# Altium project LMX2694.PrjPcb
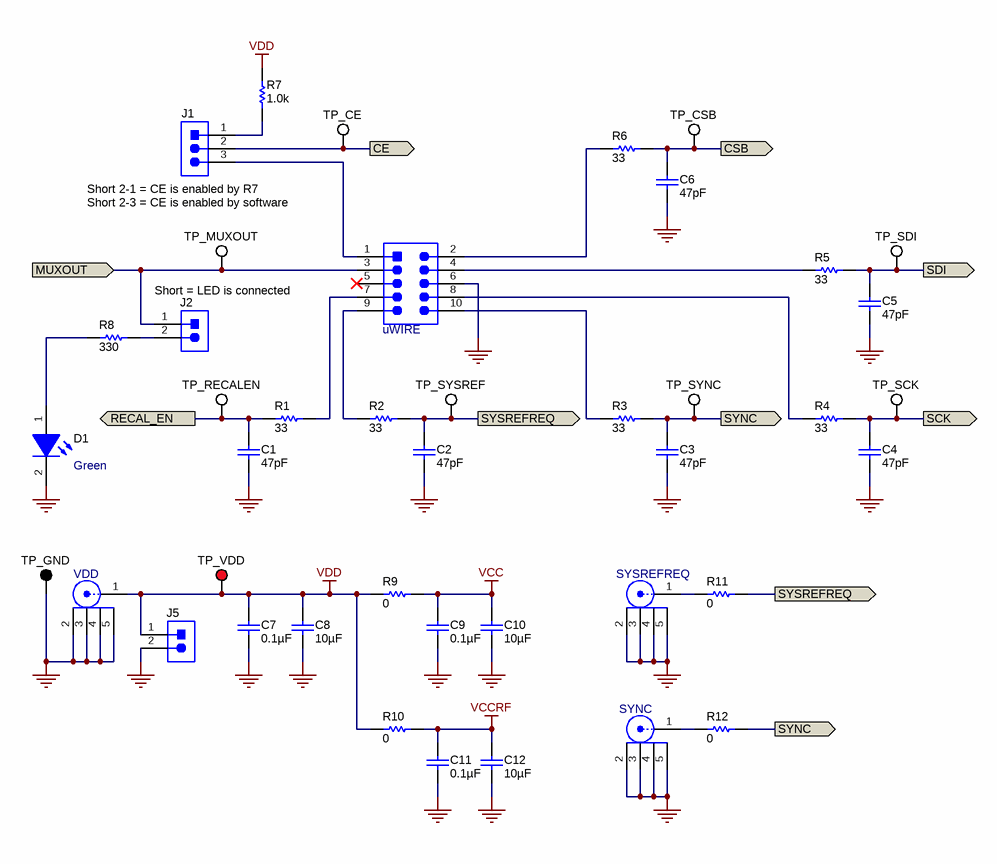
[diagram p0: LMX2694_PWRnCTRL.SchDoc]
CopyrightYear: 2019; PCB_Rev: A; PRJ_Customer: Public Release; PRJ_Title: LMX2694 EVM; SCH_Rev: A; TechSupport: http://www.ti.com/support; TID: N/A
3 sheets, 109 parts. Net scope: flat (ports and power ports of the same name join across sheets).
Board file: LMX2694.PcbDoc
Sheets:
  LMX2694_PWRnCTRL.SchDoc
  LMX2694_SYNTH.SchDoc
  LMX2694_HW.SchDoc

## Sheet LMX2694_PWRnCTRL.SchDoc: Power supply and control interface
size Letter; Date: Not shown in title block; ApprovedBy: Not shown in title block; CheckedBy: Not shown in title block; Author: Not shown in title block; CompanyName: Not shown in title block; Engineer: Not shown in title block; Organization: Not shown in title block; Address1: Not shown in title block; Address2: Not shown in title block; Address3: Not shown in title block; Address4: Not shown in title block; DocumentNumber: 1; Revision: Use project parameter SCH_Rev; SheetNumber: 1; SheetTotal: 3; PageSetup: Record=PageOptions¦CenterHorizontal=True¦CenterVertical=True¦PrintScale=1.00¦XCorrection=1.00¦YCorrection=1.00¦PrintKind=0¦BorderSize=5000000¦LeftOffset=0¦BottomOffset=0¦Orientation=2¦PaperLength=1000¦PaperWidth=1000¦Scale=100¦PaperSource=15¦PrintQuality=600¦MediaType=1¦DitherType=10¦PaperKind=Letter¦PrintScaleMode=1

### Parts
C1  ValueDisplayed: 47pF  [0402]  (hidden comment: 885012005044)
C2  ValueDisplayed: 47pF  [0402]  (hidden comment: 885012005044)
C3  ValueDisplayed: 47pF  [0402]  (hidden comment: 885012005044)
C4  ValueDisplayed: 47pF  [0402]  (hidden comment: 885012005044)
C5  ValueDisplayed: 47pF  [0402]  (hidden comment: 885012005044)
C6  ValueDisplayed: 47pF  [0402]  (hidden comment: 885012005044)
C7  ValueDisplayed: 0.1µF  [0603]  (hidden comment: 885012206046)
C8  ValueDisplayed: 10µF  [0603]  (hidden comment: GRM188R61A106KAALD)
C9  ValueDisplayed: 0.1µF  [0603]  (hidden comment: 885012206046)
C10  ValueDisplayed: 10µF  [0603]  (hidden comment: GRM188R61A106KAALD)
C11  ValueDisplayed: 0.1µF  [0603]  (hidden comment: 885012206046)
C12  ValueDisplayed: 10µF  [0603]  (hidden comment: GRM188R61A106KAALD)
D1  value Green  [LED_LTST-C190]  (hidden comment: LTST-C190GKT)
J1  TSW-103-07-G-S  [TSW-103-07-G-S]  (value not drawn)
J2  TSW-102-07-G-S  [TSW-102-07-G-S]  (value not drawn)
J3  uWIRE  [FCI_52601-S10-8LF]
J4  VDD  [FP-CON-SMA-EDGE-S_CONN_JACK-MFG]
J5  TSW-102-07-G-S  [TSW-102-07-G-S]  (value not drawn)
J6  SYSREFREQ  [FP-CON-SMA-EDGE-S_CONN_JACK-MFG]
J7  SYNC  [FP-CON-SMA-EDGE-S_CONN_JACK-MFG]
R1  ValueDisplayed: 33  [0603]  (hidden comment: CRCW060333R0JNEA)
R2  ValueDisplayed: 33  [0603]  (hidden comment: CRCW060333R0JNEA)
R3  ValueDisplayed: 33  [0603]  (hidden comment: CRCW060333R0JNEA)
R4  ValueDisplayed: 33  [0603]  (hidden comment: CRCW060333R0JNEA)
R5  ValueDisplayed: 33  [0603]  (hidden comment: CRCW060333R0JNEA)
R6  ValueDisplayed: 33  [0603]  (hidden comment: CRCW060333R0JNEA)
R7  ValueDisplayed: 1.0k  [0603]  (hidden comment: CRCW06031K00JNEA)
R8  ValueDisplayed: 330  [0603]  (hidden comment: CRCW0603330RJNEA)
R9  ValueDisplayed: 0  [0603]  (hidden comment: CRCW06030000Z0EA)
R10  ValueDisplayed: 0  [0603]  (hidden comment: CRCW06030000Z0EA)
R11  ValueDisplayed: 0  [0603]  (hidden comment: CRCW06030000Z0EA)
R12  ValueDisplayed: 0  [0603]  (hidden comment: CRCW06030000Z0EA)
TP1  TP_CE  [Keystone5002]
TP2  TP_CSB  [Keystone5002]
TP3  TP_MUXOUT  [Keystone5002]
TP4  TP_SDI  [Keystone5002]
TP5  TP_RECALEN  [Keystone5002]
TP6  TP_SYSREF  [Keystone5002]
TP7  TP_SYNC  [Keystone5002]
TP8  TP_SCK  [Keystone5002]
TP9  TP_GND  [Keystone5001]
TP10  TP_VDD  [Keystone5000]

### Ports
CE (out), CSB (out), MUXOUT (in), RECAL_EN (out), SCK (out), SDI (out), SYNC (out), SYSREFREQ (out)

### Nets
GND: C1.2 C2.2 C3.2 C4.2 C5.2 C6.2 C7.2 C8.2 C9.2 C10.2 C11.2 C12.2 D1.2(K) J3.6 J4.2 J4.3 J4.4 J4.5 J5.2 J6.2 J6.3 J6.4 J6.5 J7.2 J7.3 J7.4 J7.5 TP9.1
VCC: C9.1 C10.1 R9.2
VCCRF: C11.1 C12.1 R10.2
VDD: C7.1 C8.1 J4.1 J5.1 R7.2 R9.1 R10.1 TP10.1
CE: J1.2 TP1.1 ; port CE
CSB: C6.1 R6.2 TP2.1 ; port CSB
MUXOUT: J2.1 J3.3 TP3.1 ; port MUXOUT
RECAL_EN: C1.1 R1.1 TP5.1 ; port RECAL_EN
SCK: C4.1 R4.2 TP8.1 ; port SCK
SDI: C5.1 R5.2 TP4.1 ; port SDI
SYNC: C3.1 R3.2 R12.2 TP7.1 ; port SYNC
SYSREFREQ: C2.1 R2.2 R11.2 TP6.1 ; port SYSREFREQ
NetD1_1: D1.1(A) R8.2
NetJ1_1: J1.1 R7.1
NetJ1_3: J1.3 J3.1
NetJ2_2: J2.2 R8.1
NetJ3_2: J3.2 R6.1
NetJ3_4: J3.4 R5.1
NetJ3_7: J3.7 R1.2
NetJ3_8: J3.8 R4.1
NetJ3_9: J3.9 R2.1
NetJ3_10: J3.10 R3.1
NetJ6_1: J6.1 R11.1
NetJ7_1: J7.1 R12.1

Not connected (* = marked no-connect by the designer): J3 5*

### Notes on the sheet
- (near J1) Short 2-1 = CE is enabled by R7
- Short 2-3 = CE is enabled by software
- Short = LED is connected

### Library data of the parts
C1-C6 = CMP-0006214-2: CAP, CERM, 47 pF, 50 V, +/- 5%, C0G/NP0, 0402; Manufacturer: Wurth Elektronik; TaMin_C: -55°C; Polarized: N; SizeAreaWB_mm2: 3; Value1: Unknown; U/M: EA; Value: 47pF; TaMax_C: 125°C; SizeZ_mm: 0.6; SizeX_mm: 1; SizeY_mm: 0.5; Value2: 50V; AEC Category: Q200
C7 C9 C11 = CMP-0006829-4: CAP, CERM, 0.1 uF, 16 V, +/- 10%, X7R, 0603; Manufacturer: Wurth Elektronik; TaMin_C: -55°C; Polarized: N; SizeAreaWB_mm2: 4.68; Value1: Unknown; U/M: EA; Value: 0.1uF; TaMax_C: 125°C; SizeZ_mm: 1; SizeX_mm: 1.6; SizeY_mm: 0.8; Value2: 16V; SizeArea_mm2: 1.28; Cap_F: 100nF; AEC Category: Q200
C8 C10 C12 = CMP-0086193-1: CAP, CERM, 10 µF, 10 V,+/- 10%, X5R, 0603; Manufacturer: MuRata; SizeArea_mm2: 1.28; SizeY_mm: 0.8; TaMax_C: 85°C; TaMin_C: -55°C; VDC_V: 10V; Polarized: N; SizeAreaWB_mm2: 4.68; SizeZ_mm: 1; SizeX_mm: 1.6; AEC Category: Q200; U/M: EA; Value: 10uF
D1 = CMP-0002827-3: LED, Green, SMD; Manufacturer: Lite-On; Power_TotalModule: 100mW; Value2: 2.1V; Io_A: 20mA; Value1: 0.1W
J1 = CMP-0075407-2: Header, 100mil, 3x1, Gold, TH; Manufacturer: Samtec; Pitch_mm: 2.54; Cert_VDE: N; Gender: Male; Cert_CSA: Y; Voltage_V: 550V; Green_REACh: Passed; Current_A: 6.3A; Green_Lifecycle: Active; Row_Count: 1
J2 J5 = CMP-0075405-2: Header, 100mil, 2x1, Gold, TH; Manufacturer: Samtec; Pitch_mm: 2.54; Cert_VDE: N; Gender: Male; Cert_CSA: Y; Voltage_V: 550V; Green_REACh: Passed; Current_A: 6.3A; Green_Lifecycle: Active; Row_Count: 1
J3 = CMP-0055434-2: Header (shrouded), 100mil, 5x2, Gold, SMT; Manufacturer: FCI; PartNumber: 52601-S10-8LF; Green_Lifecycle: Active; Green_REACh: Passed
J4 J6 J7 = CMP-0088000-3: CONN SMA JACK STR EDGE MNT; Manufacturer: RF Solutions Ltd.; PartNumber: CON-SMA-EDGE-S; ContactFinish: Gold; Shrouded: true
R1-R6 = CMP-0025787-4: RES, 33, 5%, 0.1 W, AEC-Q200 Grade 0, 0603; Manufacturer: Vishay-Dale; Power_W: 100mW; TempCo: 200 ppm/C; Value_Code: 33R0; Value: 33; EIA_Code: E24; SizeX_mm: 1.6; SizeY_mm: 0.8; SizeZ_mm: 1; Value2: 0.1W; SizeArea_mm2: 1.28; AEC Qualified: Y; VDC_V: 75V; AEC Category: Q200; AEC Grade: 0
R7 = CMP-0025729-4: RES, 1.0 k, 5%, 0.1 W, AEC-Q200 Grade 0, 0603; Manufacturer: Vishay-Dale; Power_W: 100mW; TempCo: 200 ppm/C; Value_Code: 1k00; Value: 1.0k; EIA_Code: E24; Res_ohm: 1k; SizeX_mm: 1.6; SizeY_mm: 0.8; SizeZ_mm: 1; Value2: 0.1W; SizeArea_mm2: 1.28; AEC Qualified: Y; VDC_V: 75V; AEC Category: Q200; AEC Grade: 0
R8 = CMP-0025785-4: RES, 330, 5%, 0.1 W, AEC-Q200 Grade 0, 0603; Manufacturer: Vishay-Dale; Power_W: 100mW; TempCo: 200 ppm/C; Value_Code: 330R; Value: 330; EIA_Code: E24; SizeX_mm: 1.6; SizeY_mm: 0.8; SizeZ_mm: 1; Value2: 0.1W; SizeArea_mm2: 1.28; AEC Qualified: Y; VDC_V: 75V; AEC Category: Q200; AEC Grade: 0
R9-R12 = CMP-0025697-4: RES, 0, 5%, 0.1 W, AEC-Q200 Grade 0, 0603; Manufacturer: Vishay-Dale; Power_W: 100mW; TempCo: 200 ppm/C; Value_Code: 0000; Value: 0; EIA_Code: E24; SizeX_mm: 1.6; SizeY_mm: 0.8; SizeZ_mm: 1; Value2: 0.1W; SizeArea_mm2: 1.28; AEC Qualified: Y; VDC_V: 75V; AEC Category: Q200
TP1-TP8 = CMP-0055139-1: Test Point, Miniature, White, TH; Manufacturer: Keystone; CNHeader: FALSE; Green_Lifecycle: Active; Green_REACh: Passed; ContactFinish: Silver; CT: TRUE
TP9 = CMP-0055138-1: Test Point, Miniature, Black, TH; Manufacturer: Keystone; CNHeader: FALSE; Green_Lifecycle: Active; Green_REACh: Passed; ContactFinish: Silver; CT: TRUE
TP10 = CMP-0055137-1: Test Point, Miniature, Red, TH; Manufacturer: Keystone; CNHeader: FALSE; Green_Lifecycle: Active; Green_REACh: Passed; ContactFinish: Silver; CT: TRUE

## Sheet LMX2694_SYNTH.SchDoc: Synthesizer
size Letter; Date: Not shown in title block; ApprovedBy: Not shown in title block; CheckedBy: Not shown in title block; Author: Not shown in title block; CompanyName: Not shown in title block; Engineer: Not shown in title block; Organization: Not shown in title block; Address1: Not shown in title block; Address2: Not shown in title block; Address3: Not shown in title block; Address4: Not shown in title block; DocumentNumber: 2; Revision: Use project parameter SCH_Rev; SheetNumber: 2; SheetTotal: 3; PageSetup: Record=PageOptions¦CenterHorizontal=True¦CenterVertical=True¦PrintScale=1.00¦XCorrection=1.00¦YCorrection=1.00¦PrintKind=0¦BorderSize=5000000¦LeftOffset=0¦BottomOffset=0¦Orientation=2¦PaperLength=1000¦PaperWidth=1000¦Scale=100¦PaperSource=15¦PrintQuality=600¦MediaType=1¦DitherType=10¦PaperKind=Letter¦PrintScaleMode=1
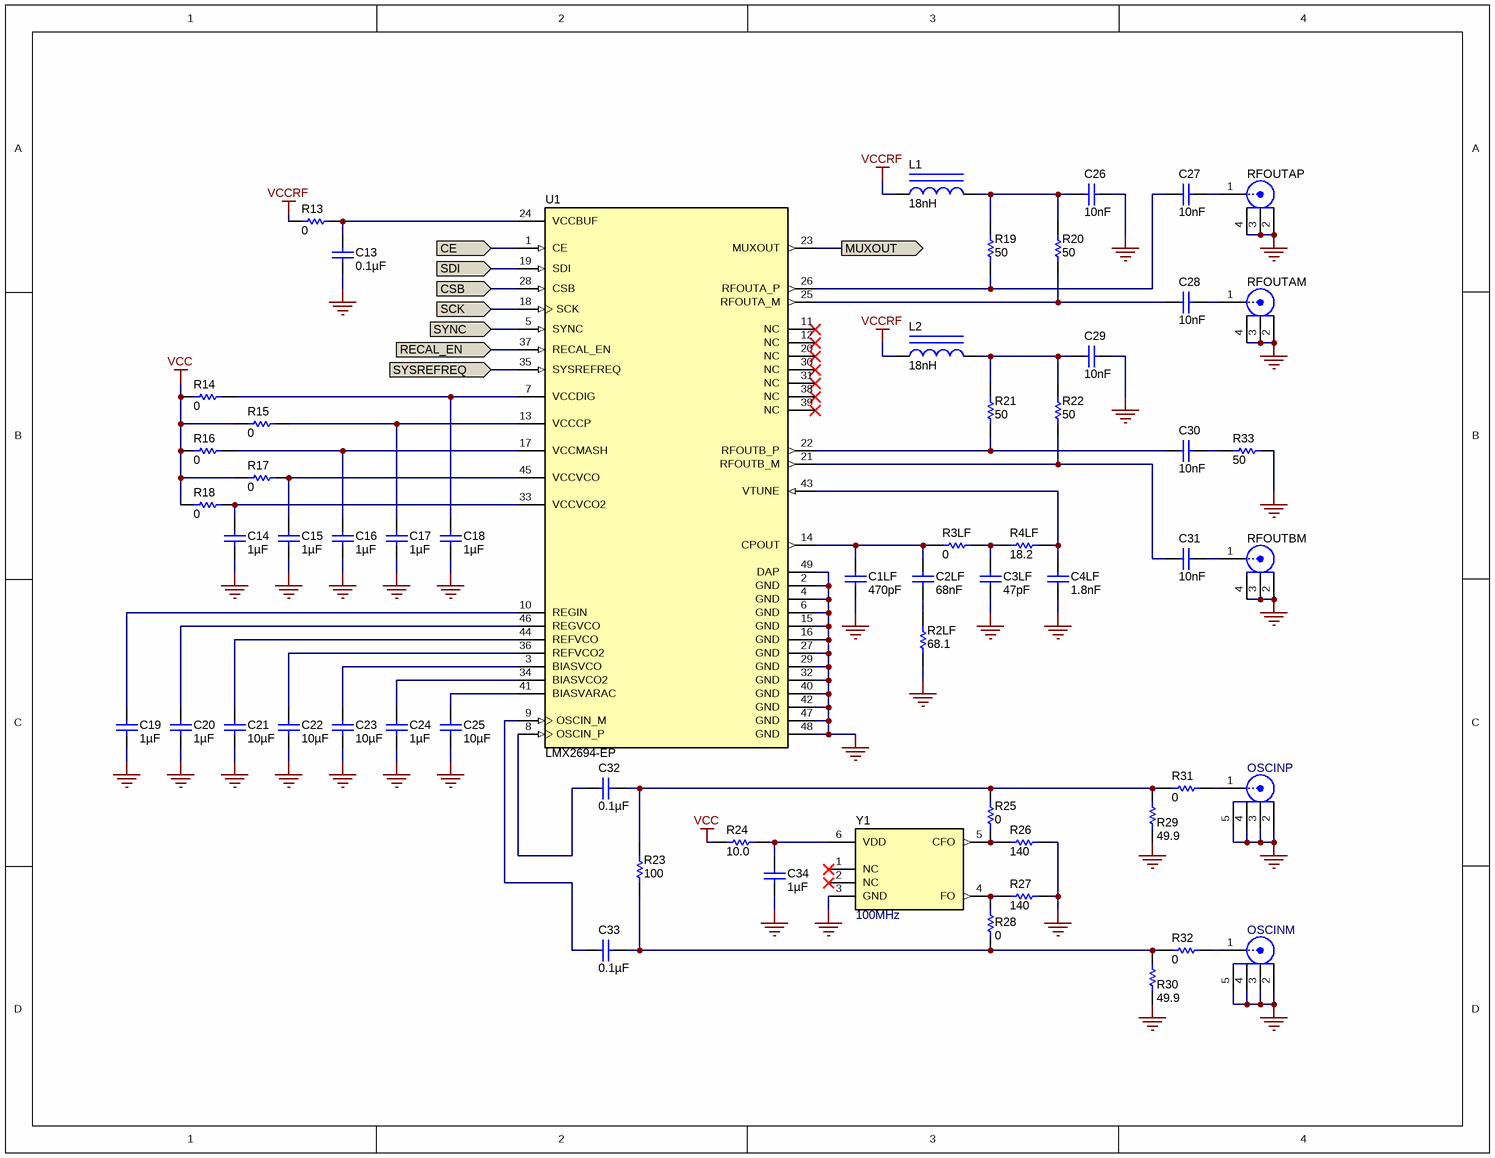
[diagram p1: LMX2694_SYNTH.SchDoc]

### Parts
C1LF  ValueDisplayed: 470pF  [0402]  (hidden comment: C0402C471K5GAC7867)
C2LF  ValueDisplayed: 68nF  [0402]  (hidden comment: CGA2B3X7R1H683K050BB)
C3LF  ValueDisplayed: 47pF  [0402]  (hidden comment: 885012005044)
C4LF  ValueDisplayed: 1.8nF  [0402]  (hidden comment: C0402C182J5RACTU)
C13  ValueDisplayed: 0.1µF  [0402]  (hidden comment: 885012205037)
C14  ValueDisplayed: 1µF  [0402]  (hidden comment: GRM155R61E105KA12D)
C15  ValueDisplayed: 1µF  [0402]  (hidden comment: GRM155R61E105KA12D)
C16  ValueDisplayed: 1µF  [0402]  (hidden comment: GRM155R61E105KA12D)
C17  ValueDisplayed: 1µF  [0402]  (hidden comment: GRM155R61E105KA12D)
C18  ValueDisplayed: 1µF  [0402]  (hidden comment: GRM155R61E105KA12D)
C19  ValueDisplayed: 1µF  [0402]  (hidden comment: GRM155R61E105KA12D)
C20  ValueDisplayed: 1µF  [0402]  (hidden comment: GRM155R61E105KA12D)
C21  ValueDisplayed: 10µF  [0603]  (hidden comment: GRM188R61A106KAALD)
C22  ValueDisplayed: 10µF  [0603]  (hidden comment: GRM188R61A106KAALD)
C23  ValueDisplayed: 10µF  [0603]  (hidden comment: GRM188R61A106KAALD)
C24  ValueDisplayed: 1µF  [0402]  (hidden comment: GRM155R61E105KA12D)
C25  ValueDisplayed: 10µF  [0603]  (hidden comment: GRM188R61A106KAALD)
C26  ValueDisplayed: 10nF  [0402_065]  (hidden comment: 520L103KT16T)
C27  ValueDisplayed: 10nF  [0402_065]  (hidden comment: 520L103KT16T)
C28  ValueDisplayed: 10nF  [0402_065]  (hidden comment: 520L103KT16T)
C29  ValueDisplayed: 10nF  [0402_065]  (hidden comment: 520L103KT16T)
C30  ValueDisplayed: 10nF  [0402_065]  (hidden comment: 520L103KT16T)
C31  ValueDisplayed: 10nF  [0402_065]  (hidden comment: 520L103KT16T)
C32  ValueDisplayed: 0.1µF  [0402]  (hidden comment: 885012205037)
C33  ValueDisplayed: 0.1µF  [0402]  (hidden comment: 885012205037)
C34  ValueDisplayed: 1µF  [0402]  (hidden comment: GRM155R61E105KA12D)
J8  RFOUTAP  [Johnson_142-0771-831]
J9  RFOUTAM  [Johnson_142-0771-831]
J10  RFOUTBM  [Johnson_142-0771-831]
J12  OSCINP  [FP-CON-SMA-EDGE-S_CONN_JACK-MFG]
J13  OSCINM  [FP-CON-SMA-EDGE-S_CONN_JACK-MFG]
L1  ValueDisplayed: 18nH  [IND_LQG15H]  (hidden comment: LQG15HS18NJ02D)
L2  ValueDisplayed: 18nH  [IND_LQG15H]  (hidden comment: LQG15HS18NJ02D)
R2LF  ValueDisplayed: 68.1  [0402]  (hidden comment: CRCW040268R1FKED)
R3LF  ValueDisplayed: 0  [0402]  (hidden comment: CRCW04020000Z0ED)
R4LF  ValueDisplayed: 18.2  [0402]  (hidden comment: CRCW040218R2FKED)
R13  ValueDisplayed: 0  [0402]  (hidden comment: CRCW04020000Z0ED)
R14  ValueDisplayed: 0  [0402]  (hidden comment: CRCW04020000Z0ED)
R15  ValueDisplayed: 0  [0402]  (hidden comment: CRCW04020000Z0ED)
R16  ValueDisplayed: 0  [0402]  (hidden comment: CRCW04020000Z0ED)
R17  ValueDisplayed: 0  [0402]  (hidden comment: CRCW04020000Z0ED)
R18  ValueDisplayed: 0  [0402]  (hidden comment: CRCW04020000Z0ED)
R19  ValueDisplayed: 50  [0402]  (hidden comment: FC0402E50R0BST1)
R20  ValueDisplayed: 50  [0402]  (hidden comment: FC0402E50R0BST1)
R21  ValueDisplayed: 50  [0402]  (hidden comment: FC0402E50R0BST1)
R22  ValueDisplayed: 50  [0402]  (hidden comment: FC0402E50R0BST1)
R23  ValueDisplayed: 100  [0402]  (hidden comment: CRCW0402100RFKED)
R24  ValueDisplayed: 10.0  [0402]  (hidden comment: CRCW040210R0FKED)
R25  ValueDisplayed: 0  [0402]  (hidden comment: CRCW04020000Z0ED)
R26  ValueDisplayed: 140  [0402]  (hidden comment: CRCW0402140RFKED)
R27  ValueDisplayed: 140  [0402]  (hidden comment: CRCW0402140RFKED)
R28  ValueDisplayed: 0  [0402]  (hidden comment: CRCW04020000Z0ED)
R29  ValueDisplayed: 49.9  [0402]  (hidden comment: CRCW040249R9FKED)
R30  ValueDisplayed: 49.9  [0402]  (hidden comment: CRCW040249R9FKED)
R31  ValueDisplayed: 0  [0402]  (hidden comment: CRCW04020000Z0ED)
R32  ValueDisplayed: 0  [0402]  (hidden comment: CRCW04020000Z0ED)
R33  ValueDisplayed: 50  [0402]  (hidden comment: FC0402E50R0BST1)
U1  LMX2694-EP  [RTC0048A]
Y1  100MHz  [Vectron_VC-708]

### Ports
CE (in), CSB (in), MUXOUT (out), RECAL_EN (in), SCK (in), SDI (in), SYNC (in), SYSREFREQ (in)

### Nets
GND: C1LF.2 C3LF.2 C4LF.2 C13.2 C14.2 C15.2 C16.2 C17.2 C18.2 C19.2 C20.2 C21.2 C22.2 C23.2 C24.2 C25.2 C26.1 C29.1 C34.2 J8.2 J8.3 J8.4 J9.2 J9.3 J9.4 J10.2 J10.3 J10.4 J12.2 J12.3 J12.4 J12.5 J13.2 J13.3 J13.4 J13.5 R2LF.1 R26.2 R27.2 R29.1 R30.1 R33.1 U1.2(GND) U1.4(GND) U1.6(GND) U1.15(GND) U1.16(GND) U1.27(GND) U1.29(GND) U1.32(GND) U1.40(GND) U1.42(GND) U1.47(GND) U1.48(GND) U1.49(DAP) Y1.3(GND)
VCC: R14.1 R15.1 R16.1 R17.1 R18.1 R24.1
VCCRF: L1.1 L2.1 R13.1
CE: U1.1(CE) ; port CE
CSB: U1.28(CSB) ; port CSB
MUXOUT: U1.23(MUXOUT) ; port MUXOUT
RECAL_EN: U1.37(RECAL_EN) ; port RECAL_EN
SCK: U1.18(SCK) ; port SCK
SDI: U1.19(SDI) ; port SDI
SYNC: U1.5(SYNC) ; port SYNC
SYSREFREQ: U1.35(SYSREFREQ) ; port SYSREFREQ
NetC1LF_1: C1LF.1 C2LF.1 R3LF.1 U1.14(CPOUT)
NetC2LF_2: C2LF.2 R2LF.2
NetC3LF_1: C3LF.1 R3LF.2 R4LF.1
NetC4LF_1: C4LF.1 R4LF.2 U1.43(VTUNE)
NetC13_1: C13.1 R13.2 U1.24(VCCBUF)
NetC14_1: C14.1 R18.2 U1.33(VCCVCO2)
NetC15_1: C15.1 R17.2 U1.45(VCCVCO)
NetC16_1: C16.1 R16.2 U1.17(VCCMASH)
NetC17_1: C17.1 R15.2 U1.13(VCCCP)
NetC18_1: C18.1 R14.2 U1.7(VCCDIG)
NetC19_1: C19.1 U1.10(REGIN)
NetC20_1: C20.1 U1.46(REGVCO)
NetC21_1: C21.1 U1.44(REFVCO)
NetC22_1: C22.1 U1.36(REFVCO2)
NetC23_1: C23.1 U1.3(BIASVCO)
NetC24_1: C24.1 U1.34(BIASVCO2)
NetC25_1: C25.1 U1.41(BIASVARAC)
NetC26_2: C26.2 L1.2 R19.2 R20.2
NetC27_1: C27.1 J8.1
NetC27_2: C27.2 R19.1 U1.26(RFOUTA_P)
NetC28_1: C28.1 J9.1
NetC28_2: C28.2 R20.1 U1.25(RFOUTA_M)
NetC29_2: C29.2 L2.2 R21.2 R22.2
NetC30_1: C30.1 R33.2
NetC30_2: C30.2 R21.1 U1.22(RFOUTB_P)
NetC31_1: C31.1 J10.1
NetC31_2: C31.2 R22.1 U1.21(RFOUTB_M)
NetC32_1: C32.1 U1.8(OSCIN_P)
NetC32_2: C32.2 R23.2 R25.2 R29.2 R31.1
NetC33_1: C33.1 U1.9(OSCIN_M)
NetC33_2: C33.2 R23.1 R28.1 R30.2 R32.1
NetC34_1: C34.1 R24.2 Y1.6(VDD)
NetJ12_1: J12.1 R31.2
NetJ13_1: J13.1 R32.2
NetR25_1: R25.1 R26.1 Y1.5(CFO)
NetR27_1: R27.1 R28.2 Y1.4(FO)

Not connected (* = marked no-connect by the designer): U1 11(NC)* 12(NC)* 20(NC)* 30(NC)* 31(NC)* 38(NC)* 39(NC)*; Y1 1(NC)* 2(NC)*

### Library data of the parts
C1LF = CMP-0860150-1: CAP, CERM, 470 pF, 50 V,+/- 10%, C0G/NP0, 0402; Manufacturer: Kemet; SizeX_mm: 1; SizeArea_mm2: 0.5; AEC Qualified: N; SizeAreaWB_mm2: 3; AEC Category: Q200; Value2: 50V; Value: 470pF; U/M: EA; SizeZ_mm: 0.6; TaMin_C: -55°C; TaMax_C: 125°C
C2LF = CMP-0006331-2: CAP, CERM, 0.068 uF, 50 V, +/- 10%, X7R, AEC-Q200 Grade 1, 0402; Manufacturer: TDK; TaMin_C: -55°C; ESR_ohm: 0.05606; Polarized: N; SizeAreaWB_mm2: 3; Value1: 0.05606 ohm; U/M: EA; TaMax_C: 125°C; SizeZ_mm: 0.6; SizeX_mm: 1; SizeY_mm: 0.5; Value2: 50V; AEC Qualified: Y; IRMS_A: 684.724mA; AEC Category: Q200
C3LF = CMP-0006214-2: as C1 on sheet LMX2694_PWRnCTRL
C4LF = CMP-0080631-1: CAP, CERM, 1800 pF, 50 V,+/- 5%, X7R, 0402; Manufacturer: Kemet; SizeAreaWB_mm2: 3; SizeArea_mm2: 0.5; AEC Qualified: N; AEC Category: Q200; Value: 1800pF; TaMax_C: 125°C; SizeZ_mm: 0.6; TaMin_C: -55°C; VDC_V: 50V; U/M: EA; SizeX_mm: 1
C13 C32 C33 = CMP-0006228-2: CAP, CERM, 0.1 uF, 16 V, +/- 10%, X7R, 0402; Manufacturer: Wurth Elektronik; TaMin_C: -55°C; Polarized: N; SizeAreaWB_mm2: 3; Value1: Unknown; U/M: EA; Value: 0.1uF; TaMax_C: 125°C; SizeZ_mm: 0.6; SizeX_mm: 1; SizeY_mm: 0.5; Value2: 16V; Cap_F: 100nF; AEC Category: Q200
C14-C20 C24 C34 = CMP-0006608-2: CAP, CERM, 1 uF, 25 V, +/- 10%, X5R, 0402; Manufacturer: MuRata; TaMin_C: -55°C; Polarized: N; SizeAreaWB_mm2: 3; Value1: Unknown; U/M: EA; Value: 1uF; TaMax_C: 85°C; SizeZ_mm: 0.6; SizeX_mm: 1; SizeY_mm: 0.5; Value2: 25V; AEC Category: Q200
C21-C23 C25 = CMP-0086193-1: as C8 on sheet LMX2694_PWRnCTRL
C26-C31 = CMP-0006210-2: CAP, CERM, 0.01 uF, 16 V, +/- 10%, X7R, 0402; Manufacturer: AT Ceramics; TaMin_C: -55°C; Polarized: N; SizeAreaWB_mm2: 3; Value1: Unknown; U/M: EA; Value: 0.01uF; TaMax_C: 125°C; SizeZ_mm: 0.65; SizeX_mm: 1; SizeY_mm: 0.5; Cap_Case: 0402; Value2: 16V; AEC Category: Q200
J8-J10 = CMP-0055844-2: JACK, SMA, 50 Ohm, Gold, Edge Mount; PartNumber: 142-0771-831; Manufacturer: Cinch Connectivity; Voltage_V: 170V; Gender: Female
J12 J13 = CMP-0088000-3: as J4 on sheet LMX2694_PWRnCTRL
L1 L2 = CMP-0058614-1: Inductor, Multilayer, Air Core, 18 nH, 0.3 A, 0.36 ohm, SMD; Manufacturer: MuRata; Isat: 0.3A @ % inductance drop; Irms: 0.3A @ C rise; Green_Lifecycle: Active; SizeAreaWB_mm2: 3; DCR_ohm: 0.36; Green_REACh: Passed; Value: 18nH; Imax_A: 300mA; SizeZ_mm: 0.55; SizeX_mm: 1; SizeY_mm: 0.5; Value2: 0.3A; AEC Category: Q200
R2LF = CMP-0026507-2: RES, 68.1, 1%, 0.063 W, AEC-Q200 Grade 0, 0402; Manufacturer: Vishay-Dale; Power_W: 63mW; TempCo: 100 ppm/C; Value_Code: 68R1; Value: 68.1; EIA_Code: E96; SizeX_mm: 1; SizeY_mm: 0.5; SizeZ_mm: 0.6; Value2: 0.063W; AEC Qualified: Y; VDC_V: 50V; AEC Category: Q200; AEC Grade: 0
R3LF R13-R18 R25 R28 R31 R32 = CMP-0026822-3: RES, 0, 5%, 0.063 W, AEC-Q200 Grade 0, 0402; Manufacturer: Vishay-Dale; Power_W: 63mW; TempCo: 200 ppm/C; Value_Code: 0000; Value: 0; EIA_Code: E24; SizeX_mm: 1; SizeY_mm: 0.5; SizeZ_mm: 0.6; Value2: 0.063W; AEC Qualified: Y; VDC_V: 50V; AEC Category: Q200
R4LF = CMP-0026061-3: RES, 18.2, 1%, 0.063 W, AEC-Q200 Grade 0, 0402; Manufacturer: Vishay-Dale; Power_W: 63mW; TempCo: 100 ppm/C; Value_Code: 18R2; Value: 18.2; EIA_Code: E96; SizeX_mm: 1; SizeY_mm: 0.5; SizeZ_mm: 0.6; Value2: 0.063W; AEC Qualified: Y; VDC_V: 50V; AEC Category: Q200; AEC Grade: 0
R19-R22 R33 = CMP-0026791-1: RES, 50, 0.1%, 0.05 W, 0402; Manufacturer: Vishay-Dale; Power_W: 50mW; TempCo: 25 ppm/C; Value_Code: 50R0; U/M: EA; Value: 50; SizeX_mm: 1; SizeY_mm: 0.5; SizeZ_mm: 0.6; Value2: 0.05W; AEC Qualified: N; AEC Category: Q200
R23 = CMP-0025951-3: RES, 100, 1%, 0.063 W, AEC-Q200 Grade 0, 0402; Manufacturer: Vishay-Dale; Power_W: 63mW; TempCo: 100 ppm/C; Value_Code: 100R; Value: 100; EIA_Code: E96; SizeX_mm: 1; SizeY_mm: 0.5; SizeZ_mm: 0.6; Value2: 0.063W; AEC Qualified: Y; VDC_V: 50V; AEC Category: Q200; AEC Grade: 0
R24 = CMP-0025963-3: RES, 10.0, 1%, 0.063 W, AEC-Q200 Grade 0, 0402; Manufacturer: Vishay-Dale; Power_W: 63mW; TempCo: 100 ppm/C; Value_Code: 10R0; Value: 10.0; EIA_Code: E96; Res_ohm: 10; SizeX_mm: 1; SizeY_mm: 0.5; SizeZ_mm: 0.6; Value2: 0.063W; AEC Qualified: Y; VDC_V: 50V; AEC Category: Q200; AEC Grade: 0
R26 R27 = CMP-0026010-3: RES, 140, 1%, 0.063 W, AEC-Q200 Grade 0, 0402; Manufacturer: Vishay-Dale; Power_W: 63mW; TempCo: 100 ppm/C; Value_Code: 140R; Value: 140; EIA_Code: E96; SizeX_mm: 1; SizeY_mm: 0.5; SizeZ_mm: 0.6; Value2: 0.063W; AEC Qualified: Y; VDC_V: 50V; AEC Category: Q200; AEC Grade: 0
R29 R30 = CMP-0026404-2: RES, 49.9, 1%, 0.063 W, AEC-Q200 Grade 0, 0402; Manufacturer: Vishay-Dale; Power_W: 63mW; TempCo: 100 ppm/C; Value_Code: 49R9; Value: 49.9; EIA_Code: E96; SizeX_mm: 1; SizeY_mm: 0.5; SizeZ_mm: 0.6; Value2: 0.063W; AEC Qualified: Y; VDC_V: 50V; AEC Category: Q200; AEC Grade: 0
U1 = CMP-0080714-4: 15-GHz Wideband PLLatinum™ RF Synthesizer With Phase Synchronization, RTC0048A (PVQFN-64); Manufacturer: Texas Instruments; AEC Qualified: N; SizeAreaWB_mm2: 81; SizeArea_mm2: 49; CompType: IC; SizeY_mm: 7; SizeZ_mm: 0.9; AEC Category: Q200
Y1 = CMP-0006121-3: Crystal Oscillator, 100 MHz, LVDS, 3.3V, SMD; Manufacturer: Vectron; PartNumber: VC-708-EDE-FNXN-100M000000; TaMin_C: -40°C; Frequency Stability: +/-25ppm; SizeAreaWB_mm2: 63; TaMax_C: 85°C; SizeZ_mm: 1.8; SizeX_mm: 5; SizeY_mm: 7; SizeArea_mm2: 35

## Sheet LMX2694_HW.SchDoc: Hardware
size Letter; Date: Not shown in title block; ApprovedBy: Not shown in title block; CheckedBy: Not shown in title block; Author: Not shown in title block; CompanyName: Not shown in title block; Engineer: Not shown in title block; Organization: Not shown in title block; Address1: Not shown in title block; Address2: Not shown in title block; Address3: Not shown in title block; Address4: Not shown in title block; DocumentNumber: 3; Revision: Use project parameter SCH_Rev; SheetNumber: 3; SheetTotal: 3; PageSetup: Record=PageOptions¦CenterHorizontal=True¦CenterVertical=True¦PrintScale=1.00¦XCorrection=1.00¦YCorrection=1.00¦PrintKind=0¦BorderSize=5000000¦LeftOffset=0¦BottomOffset=0¦Orientation=2¦PaperLength=1000¦PaperWidth=1000¦Scale=100¦PaperSource=15¦PrintQuality=600¦MediaType=1¦DitherType=10¦PaperKind=Letter¦PrintScaleMode=1
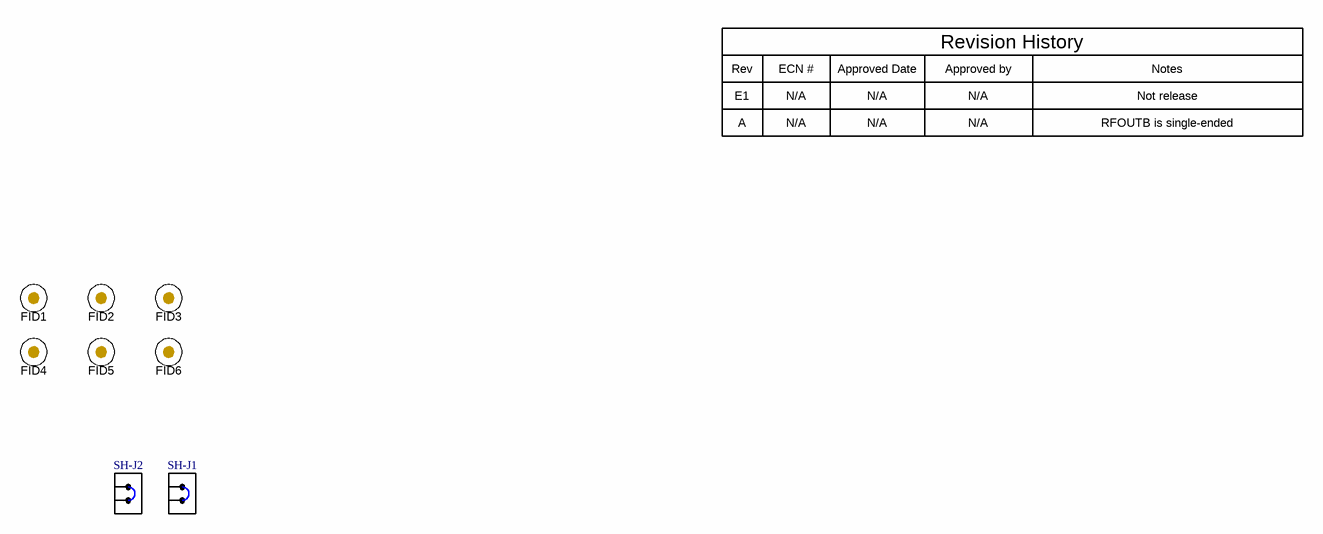
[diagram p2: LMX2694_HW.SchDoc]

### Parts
FID1  Fiducial  [Fiducial10-20]  (value not drawn)
FID2  Fiducial  [Fiducial10-20]  (value not drawn)
FID3  Fiducial  [Fiducial10-20]  (value not drawn)
FID4  Fiducial  [Fiducial10-20]  (value not drawn)
FID5  Fiducial  [Fiducial10-20]  (value not drawn)
FID6  Fiducial  [Fiducial10-20]  (value not drawn)
SH-J1  SNT-100-BK-G  [SNT-100-BK-G]  (value not drawn)
SH-J2  SNT-100-BK-G  [SNT-100-BK-G]  (value not drawn)

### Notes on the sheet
- Rev
- E1
- ECN #
- N/A
- Approved Date
- Approved by
- Revision History
- Notes
- Not release
- A
- RFOUTB is single-ended

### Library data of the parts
FID1-FID6 = CMP-0077181-1: Fiducial mark.  There is nothing to buy or mount.
SH-J1 SH-J2 = CMP-0003623-3: Shunt, 100mil, Gold plated, Black; Alternate PartNumber: 969102-0000-DA; Manufacturer: Samtec; Alternate Manufacturer: 3M; Value: 1x2; Note: You can "mate" this to a header by matching the designator.  i.e. use SH-J3 for header J3

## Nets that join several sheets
GND: LMX2694_PWRnCTRL (28 pins), LMX2694_SYNTH (56 pins)
VCC: LMX2694_PWRnCTRL (C9.1 C10.1 R9.2), LMX2694_SYNTH (6 pins)
VCCRF: LMX2694_PWRnCTRL (C11.1 C12.1 R10.2), LMX2694_SYNTH (L1.1 L2.1 R13.1)
CE: LMX2694_PWRnCTRL (J1.2 TP1.1), LMX2694_SYNTH (U1.1)
CSB: LMX2694_PWRnCTRL (C6.1 R6.2 TP2.1), LMX2694_SYNTH (U1.28)
MUXOUT: LMX2694_PWRnCTRL (J2.1 J3.3 TP3.1), LMX2694_SYNTH (U1.23)
RECAL_EN: LMX2694_PWRnCTRL (C1.1 R1.1 TP5.1), LMX2694_SYNTH (U1.37)
SCK: LMX2694_PWRnCTRL (C4.1 R4.2 TP8.1), LMX2694_SYNTH (U1.18)
SDI: LMX2694_PWRnCTRL (C5.1 R5.2 TP4.1), LMX2694_SYNTH (U1.19)
SYNC: LMX2694_PWRnCTRL (C3.1 R3.2 R12.2 TP7.1), LMX2694_SYNTH (U1.5)
SYSREFREQ: LMX2694_PWRnCTRL (C2.1 R2.2 R11.2 TP6.1), LMX2694_SYNTH (U1.35)

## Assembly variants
001: not fitted C3LF C34 FID1 FID2 FID3 FID4 FID5 FID6 J4 J6 J7 R1 R11 R12 R23 R24 R25 R26 R27 R28 R32 Y1
002: not fitted C3LF C34 FID1 FID2 FID3 FID4 FID5 FID6 J4 J6 J7 R11 R12 R23 R24 R25 R26 R27 R28 R32 Y1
